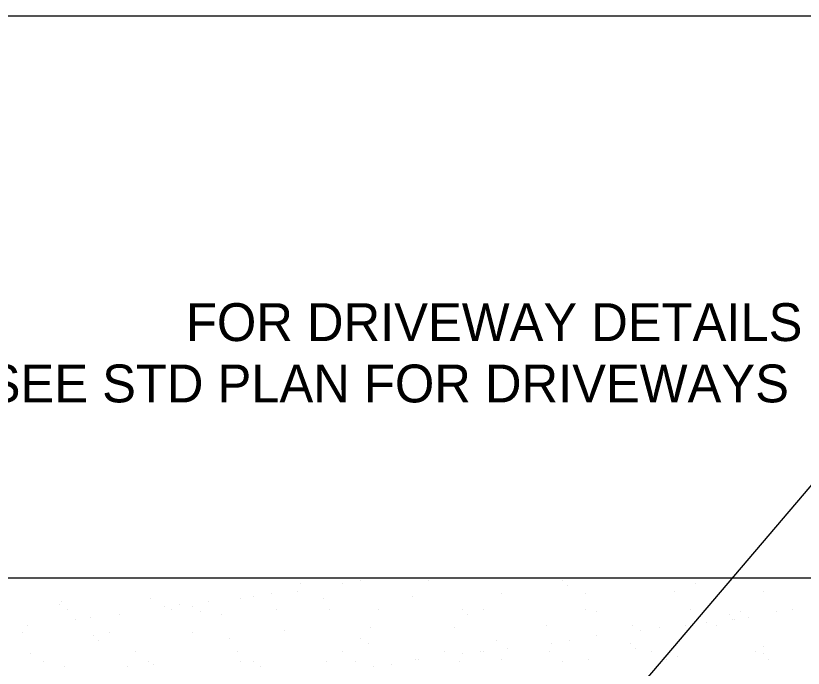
# Model space of a CAD drawing. Extents: x -118779 to -116979, y -104389 to -102939.
# Drawn here: x -118334.6 to -118209.8, y -103042.6 to -102939.3 of the extents above; entities that cross this region are included whole.
import ezdxf

# ---------------------------------------------------------------- set-up
doc = ezdxf.new("R2010")
doc.units = 0
for name, color, linetype in [('Default', 7, 'Continuous'), ('G-MARK', 7, 'Continuous'), ('Misc CnstDet(22)', 7, 'Continuous')]:
    doc.layers.add(name, color=color, linetype=linetype)

msp = doc.modelspace()

# ---------------------------------------------------------------- linework, layer by layer
at = {"layer": 'Default'}
msp.add_lwpolyline([(-118779.39, -102939.25), (-116979.39, -102939.25), (-116979.39, -104389.25), (-118779.39, -104389.25)], close=True, dxfattribs=at)
at = {"layer": 'G-MARK'}
msp.add_lwpolyline([(-118244.71, -103056.13), (-118194.52, -102997.23), (-118201.99, -102997.23)], dxfattribs=at)
at = {"layer": 'Misc CnstDet(22)'}
for p, q in [((-118334.3, -103028.34), (-118334.3, -103028.34)), ((-118332.22, -103028.34), (-118332.22, -103028.34)), ((-118317.71, -103028.34), (-118317.71, -103028.34)), ((-118301.53, -103028.34), (-118301.53, -103028.34)), ((-118289.5, -103029.17), (-118289.5, -103029.17)), ((-118284.94, -103028.34), (-118284.94, -103028.34)), ((-118282.87, -103029.17), (-118282.87, -103029.17)), ((-118279.96, -103028.75), (-118279.96, -103028.75)), ((-118275.82, -103028.34), (-118275.82, -103028.34)), ((-118269.18, -103028.75), (-118269.18, -103028.75)), ((-118268.77, -103028.34), (-118268.77, -103028.34)), ((-118252.18, -103028.34), (-118252.18, -103028.34)), ((-118248.03, -103028.75), (-118248.03, -103028.75)), ((-118236, -103028.34), (-118236, -103028.34)), ((-118226.87, -103029.17), (-118226.87, -103029.17)), ((-118219.41, -103028.34), (-118219.41, -103028.34)), ((-118289.92, -103030.41), (-118289.92, -103030.41)), ((-118247.2, -103029.58), (-118247.2, -103029.58)), ((-118230.19, -103030.41), (-118230.19, -103030.41)), ((-118216.09, -103030.41), (-118216.09, -103030.41)), ((-118313.15, -103031.66), (-118313.15, -103031.66)), ((-118299.04, -103031.66), (-118299.04, -103031.66)), ((-118296.97, -103031.24), (-118296.97, -103031.24)), ((-118294.07, -103030.83), (-118294.07, -103030.83)), ((-118285.77, -103031.66), (-118285.77, -103031.66)), ((-118271.67, -103031.24), (-118271.67, -103031.24)), ((-118257.57, -103030.83), (-118257.57, -103030.83)), ((-118244.3, -103030.83), (-118244.3, -103030.83)), ((-118327.66, -103032.48), (-118327.66, -103032.48)), ((-118327.25, -103032.07), (-118327.25, -103032.07)), ((-118311.07, -103032.9), (-118311.07, -103032.9)), ((-118308.58, -103032.48), (-118308.58, -103032.48)), ((-118306.51, -103032.9), (-118306.51, -103032.9)), ((-118304.02, -103032.07), (-118304.02, -103032.07)), ((-118326.42, -103033.31), (-118326.42, -103033.31)), ((-118318.12, -103034.14), (-118318.12, -103034.14)), ((-118309.83, -103033.31), (-118309.83, -103033.31)), ((-118305.27, -103033.73), (-118305.27, -103033.73)), ((-118301.95, -103034.14), (-118301.95, -103034.14)), ((-118293.24, -103033.31), (-118293.24, -103033.31)), ((-118284.94, -103033.31), (-118284.94, -103033.31)), ((-118277.06, -103033.31), (-118277.06, -103033.31)), ((-118263.79, -103033.31), (-118263.79, -103033.31)), ((-118262.96, -103034.14), (-118262.96, -103034.14)), ((-118260.47, -103033.31), (-118260.47, -103033.31)), ((-118244.3, -103033.31), (-118244.3, -103033.31)), ((-118242.64, -103033.73), (-118242.64, -103033.73)), ((-118227.7, -103033.31), (-118227.7, -103033.31)), ((-118221.48, -103034.14), (-118221.48, -103034.14)), ((-118219.82, -103033.73), (-118219.82, -103033.73)), ((-118214.02, -103033.73), (-118214.02, -103033.73)), ((-118211.53, -103033.31), (-118211.53, -103033.31)), ((-118325.17, -103034.97), (-118325.17, -103034.97)), ((-118322.69, -103034.56), (-118322.69, -103034.56)), ((-118225.22, -103035.39), (-118225.22, -103035.39)), ((-118221.07, -103034.97), (-118221.07, -103034.97)), ((-118220.65, -103034.97), (-118220.65, -103034.97)), ((-118218.58, -103034.56), (-118218.58, -103034.56)), ((-118332.64, -103035.8), (-118332.64, -103035.8)), ((-118291.99, -103036.63), (-118291.99, -103036.63)), ((-118278.31, -103036.22), (-118278.31, -103036.22)), ((-118265.03, -103036.22), (-118265.03, -103036.22)), ((-118250.52, -103035.8), (-118250.52, -103035.8)), ((-118236.83, -103035.8), (-118236.83, -103035.8)), ((-118235.58, -103036.63), (-118235.58, -103036.63)), ((-118232.68, -103036.22), (-118232.68, -103036.22)), ((-118228.53, -103035.8), (-118228.53, -103035.8)), ((-118223.56, -103035.8), (-118223.56, -103035.8)), ((-118333.47, -103037.05), (-118333.47, -103037.05)), ((-118322.27, -103037.46), (-118322.27, -103037.46)), ((-118319.78, -103037.05), (-118319.78, -103037.05)), ((-118306.51, -103037.05), (-118306.51, -103037.05)), ((-118300.7, -103037.88), (-118300.7, -103037.88)), ((-118279.96, -103037.88), (-118279.96, -103037.88)), ((-118242.64, -103037.46), (-118242.64, -103037.46)), ((-118321.44, -103038.29), (-118321.44, -103038.29)), ((-118278.72, -103038.71), (-118278.72, -103038.71)), ((-118258.4, -103038.29), (-118258.4, -103038.29)), ((-118249.69, -103038.71), (-118249.69, -103038.71)), ((-118246.78, -103038.29), (-118246.78, -103038.29)), ((-118246.78, -103038.29), (-118246.78, -103038.29)), ((-118237.24, -103038.71), (-118237.24, -103038.71)), ((-118216.09, -103039.12), (-118216.09, -103039.12)), ((-118332.22, -103040.37), (-118332.22, -103040.37)), ((-118315.63, -103039.95), (-118315.63, -103039.95)), ((-118299.46, -103039.95), (-118299.46, -103039.95)), ((-118282.87, -103039.95), (-118282.87, -103039.95)), ((-118266.69, -103039.95), (-118266.69, -103039.95)), ((-118263.79, -103040.37), (-118263.79, -103040.37)), ((-118260.89, -103039.95), (-118260.89, -103039.95)), ((-118260.47, -103039.95), (-118260.47, -103039.95)), ((-118256.74, -103039.54), (-118256.74, -103039.54)), ((-118250.1, -103039.95), (-118250.1, -103039.95)), ((-118236.41, -103039.54), (-118236.41, -103039.54)), ((-118233.93, -103039.95), (-118233.93, -103039.95)), ((-118217.34, -103039.95), (-118217.34, -103039.95)), ((-118216.09, -103040.37), (-118216.09, -103040.37)), ((-118330.15, -103041.61), (-118330.15, -103041.61)), ((-118313.56, -103041.61), (-118313.56, -103041.61)), ((-118299.04, -103041.61), (-118299.04, -103041.61)), ((-118296.97, -103041.61), (-118296.97, -103041.61)), ((-118285.36, -103041.61), (-118285.36, -103041.61)), ((-118280.79, -103041.61), (-118280.79, -103041.61)), ((-118271.25, -103041.19), (-118271.25, -103041.19)), ((-118270.84, -103041.19), (-118270.84, -103041.19)), ((-118264.2, -103041.61), (-118264.2, -103041.61)), ((-118257.57, -103041.19), (-118257.57, -103041.19)), ((-118248.03, -103041.61), (-118248.03, -103041.61)), ((-118243.88, -103041.19), (-118243.88, -103041.19)), ((-118231.44, -103041.19), (-118231.44, -103041.19)), ((-118229.78, -103040.78), (-118229.78, -103040.78)), ((-118215.26, -103041.19), (-118215.26, -103041.19)), ((-118326.83, -103042.44), (-118326.83, -103042.44)), ((-118316.88, -103042.44), (-118316.88, -103042.44)), ((-118312.73, -103042.02), (-118312.73, -103042.02)), ((-118295.73, -103042.44), (-118295.73, -103042.44)), ((-118277.89, -103042.44), (-118277.89, -103042.44)), ((-118274.99, -103042.02), (-118274.99, -103042.02))]:
    msp.add_line(p, q, dxfattribs=at)
msp.add_lwpolyline([(-118415.18, -103028.34), (-118094.15, -103028.34)], dxfattribs=at)

# ---------------------------------------------------------------- texts
for s, p in [('FOR DRIVEWAY DETAILS', (-118307.6, -102990.8)), ('SEE STD PLAN FOR DRIVEWAYS', (-118339.16, -103000.52))]:
    msp.add_text(s, height=6, dxfattribs=at).set_placement(p)

doc.saveas('drawing.dxf')
